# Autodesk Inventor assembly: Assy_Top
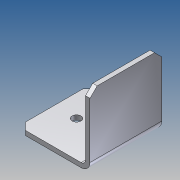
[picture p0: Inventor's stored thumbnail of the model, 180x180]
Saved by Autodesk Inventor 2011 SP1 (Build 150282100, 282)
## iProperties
Created: 2013-10
Part Number: Assy_Top
Document SubType Name: Assembly
Designer: Ralph.Nemitz
Author: Ralph.Nemitz
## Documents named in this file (2)
- C:\Users\Ralph.Nemitz\Documents\Inventor\Regeltest\Assy_Top.iam
- C:\Users\Ralph.Nemitz\Documents\Inventor\Regeltest\Subassy_1.iam
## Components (1 placed, 1 different names)
1. Subassy_1:1 [sub-assembly]
